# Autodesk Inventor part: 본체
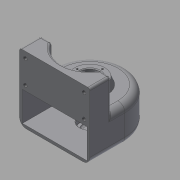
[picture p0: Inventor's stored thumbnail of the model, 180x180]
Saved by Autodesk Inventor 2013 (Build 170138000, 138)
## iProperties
Created: 2015-02
Part Number: 본체
Material: 일반
Document SubType Name: Modeling
Designer: Administrator
Density: 1 g/cm^3
Author: Administrator
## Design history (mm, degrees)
sketch "스케치1"
  geometry: L1 (-50, 0)-(-50, -50); L2 (50, 0)-(50, -50); L3 (-50, -50)-(50, -50); A1 r 50 centre (0, 0) between (50, 0) and (-50, 0); 1 further point
  constraints: 6 end point, 2 point on circle, 2 tangent, 1 centre point, 1 coincident, 1 parallel, 1 perpendicular, 1 vertical
  dimensions: "d0" = 100 diameter of A1; "d1" = 50 distance from line of L3 point (0, 0)
extrude "돌출1" new body sketch "스케치1" distance "d2" = 50; taper "d3" = 0 deg
feature "쉘1" dims "d4" = 4
sketch "스케치3"
  geometry: L1 (0, 4)-(0, 46) reference; L2 (0, 0)-(0, 50) reference; L3 (50, 50)-(0, 50) reference; L4 (0, 50)-(-50, 50) reference; L5 (0, 50)-(0, 60); L6 (0, 60)-(-21.36, 60); L7 (-21.36, 60)-(-25, 50); L8 (0, 0)-(0, -9); L9 (0, -9)-(-20, -9); L10 (-20, -9)-(-20, 0); L11 (-20, 0)-(0, 0)
  constraints: 14 end point, 6 perpendicular, 1 midpoint
  dimensions: "d5" = 10 distance of L2.end L5.end; "d6" = 110 deg angle of L4 L7; "d7" = 50 diameter of L7.end L5; "d9" = 9 distance of L2.start L8.end; "d10" = 40 diameter of L10 L8
revolve "회전2" stored, may be unused: angle "d11" = 90 deg
sketch "스케치6"
  geometry: L1 (100, 0)-(0, 0) reference; L2 (100, 0)-(100, 50) reference; L3 (0, 50)-(100, 50) reference; L4 (0, 0)-(0, 50) reference; L5 (0, 0)-(0, 95); L6 (0, 95)-(100, 95); L7 (100, 95)-(100, 0); 1 further point
  constraints: 6 end point, 1 collinear, 1 parallel, 1 perpendicular
  dimensions: "d52" = 95 distance of L1.end L5.end
extrude "돌출2" join sketch "스케치6" distance "d53" = 30; taper "d54" = 0 deg
sketch "스케치7"
  geometry: L1 (-50, -20)-(50, -20) reference; L2 (50, 0)-(50, -20) reference; L3 (-50, -20)-(-50, 0) reference; L4 (-50, -50)-(-50, -20) reference; L5 (50, -50)-(-50, -50) reference; L6 (50, -20)-(50, -50) reference; L7 (-50, -20)-(50, -20) reference; L8 (34.641, -20)-(-34.641, -20); A1 r 50 centre (0, 0) between (50, 0) and (-50, 0) reference; A2 r 40 centre (0, 0) between (-34.641, -20) and (34.641, -20); A3 r 50 centre (0, 0) between (50, 0) and (-50, 0) reference; 1 further point
  constraints: 2 end point, 2 point on circle, 1 centre point, 1 coincident, 1 collinear, 1 point on line
  dimensions: "d55" = 80 diameter of A2
extrude "돌출3" cut sketch "스케치7" stored distance "d56" = 30; taper "d57" = 0 deg
sketch "스케치8"
  geometry: L1 (100, 95)-(0, 95) reference; L2 (0, 0)-(0, 95) reference; 5 further points
  constraints: 2 horizontal alignment, 2 vertical alignment
  dimensions: "d58" = 33 distance of point (91.75, 53) point (91.75, 86); "d60" = 9 distance from line of L1 point (91.75, 86); "d61" = 83.5 distance of point (8.25, 86) point (91.75, 86); "d62" = 8.25 distance from line of L2 point (8.25, 86)
hole "구멍5" sketch "스케치8" at (8.25, 86), (91.75, 86), (91.75, 53), (8.25, 53) diameter "d63" = 5.134; stored, may be unused: countersink angle "d67" = 90 deg, drill point angle "d69" = 118 deg; dims "d64" = 10, "d65" = 4, "d66" = 2, "d68" = 13
fillet "모깎기1" dims "d71" = 3
revolve "회전3" stored, may be unused: angle "d73" = 90 deg
hole "구멍6" diameter "d76" = 20; stored, may be unused: countersink angle "d80" = 90 deg, drill point angle "d82" = 0 deg; dims "d74" = 10, "d75" = 10, "d77" = 10, "d78" = 4, "d79" = 2, "d81" = 66
hole "구멍7" diameter "d85" = 28; stored, may be unused: countersink angle "d89" = 90 deg, drill point angle "d91" = 0 deg; dims "d83" = 10, "d84" = 10, "d86" = 10, "d87" = 4, "d88" = 2, "d90" = 10
hole "구멍8" diameter "d94" = 28; stored, may be unused: countersink angle "d98" = 90 deg, drill point angle "d100" = 0 deg; dims "d92" = 10, "d93" = 10, "d95" = 10, "d96" = 4, "d97" = 2, "d99" = 8
sketch "스케치9"
  geometry: C1 r 14 at (0, 0) reference; 1 further point
  constraints: 1 vertical alignment
  dimensions: "d101" = 18 distance of C1.centre point (0, 18)
hole "구멍9" sketch "스케치9" at (0, 18) diameter "d102" = 2.459; stored, may be unused: countersink angle "d106" = 90 deg, drill point angle "d108" = 118 deg; dims "d103" = 6, "d104" = 4, "d105" = 2, "d107" = 9
fillet "모깎기3" dims "d112" = 10
chamfer "모따기1" distance "d113" = 1; stored, may be unused: second distance "d114" = 2, angle "d115" = 45 deg
fillet "모깎기4" dims "d116" = 0.3
fillet "모깎기5" dims "d117" = 3
node "작업 평면3"
sketch "스케치10"
  geometry: L1 (40, 0)-(-40, 0) reference; 2 further points
  constraints: 1 vertical alignment, 1 other
  dimensions: "d118" = 25 distance from line of point (0, 25) L1
feature "엠보싱1" sketch "스케치10" dims "d0" = 100, "d1" = 50, "d5" = 10, "d6" = 110 deg, "d7" = 50, "d9" = 9, "d10" = 40, "d119" = 0.5, "d120" = 0
fillet "모깎기6" dims "d121" = 3
node "솔리드1"
pattern_circular "원형 패턴2" dims angle "d110" = 360 deg
node "절단 모서리 투영1"
